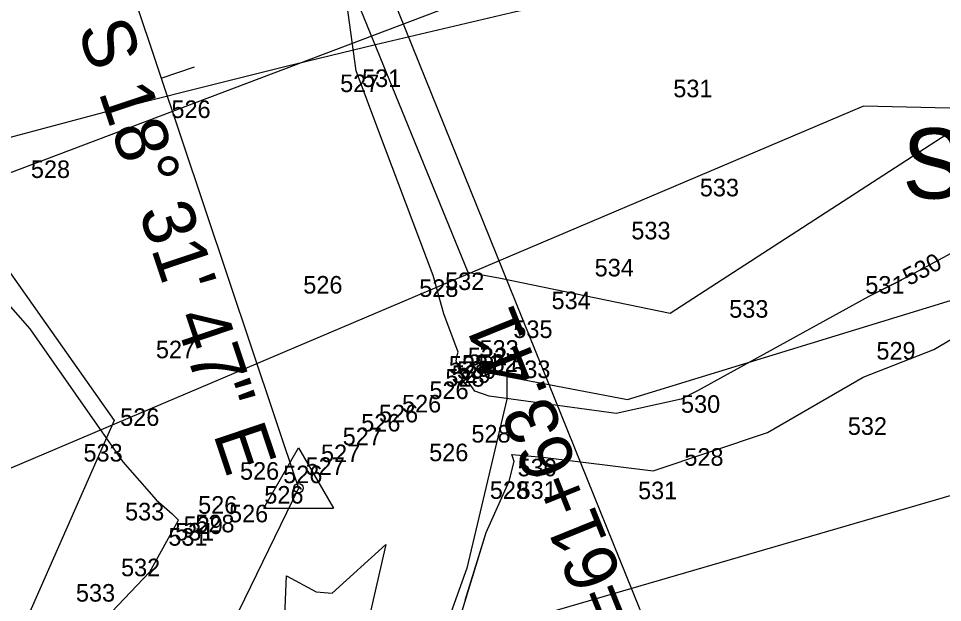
# Model space of a CAD drawing. Extents: x 1787461 to 1970323, y 938412 to 1118748.
# Drawn here: x 1967816.7 to 1967921.9, y 1117796.9 to 1117863.4 of the extents above; entities that cross this region are included whole.
import ezdxf

# ---------------------------------------------------------------- set-up
doc = ezdxf.new("R2010")
doc.units = 0
for name, color, linetype in [('Default', 7, 'Continuous'), ('HHA ADDITIONAL XSs', 7, 'Continuous'), ('Level 1', 7, 'Continuous'), ('RD_EX_DV_Prop', 7, 'Continuous'), ('RD_EX_H2O', 7, 'Continuous'), ('RD_EX_VEG', 7, 'Continuous'), ('RD_HC_CL', 7, 'Continuous'), ('RD_HC_CL_Rel', 7, 'Continuous'), ('RD_HC_Data', 7, 'Continuous'), ('RD_HC_Data_Tic', 7, 'Continuous'), ('RD_PD_Final_TrvlWay', 7, 'Continuous'), ('RD_SMD_Locator', 7, 'Continuous')]:
    doc.layers.add(name, color=color, linetype=linetype)

msp = doc.modelspace()

# ---------------------------------------------------------------- linework, layer by layer
at = {"layer": 'Default'}
for points in [[(1967867.59, 1117797.18), (1967869.95, 1117804.92), (1967872.58, 1117810.73), (1967873.16, 1117812.99), (1967872.89, 1117813.79), (1967876.43, 1117813.48), (1967888.97, 1117811.92), (1967902.02, 1117816.29), (1967912.9, 1117822.59), (1967920.97, 1117825.73), (1967929.46, 1117830.76), (1967935.78, 1117834.28), (1967952.17, 1117841.31), (1967957.87, 1117844.34), (1967974.87, 1117851.66), (1967974.98, 1117851.71), (1967977.62, 1117853.39), (1967984.02, 1117858.79), (1967988.88, 1117861.65), (1968005.7, 1117871.25), (1968008.59, 1117872.94), (1968022.11, 1117880.66), (1968026.51, 1117882.61), (1968036.54, 1117886.88)], [(1967867.59, 1117797.18), (1967869.95, 1117804.92), (1967872.58, 1117810.73), (1967873.16, 1117812.99), (1967872.89, 1117813.79), (1967876.43, 1117813.48), (1967888.97, 1117811.92), (1967902.02, 1117816.29), (1967912.9, 1117822.59), (1967920.97, 1117825.73), (1967929.46, 1117830.76), (1967935.78, 1117834.28), (1967952.17, 1117841.31), (1967957.87, 1117844.34), (1967974.87, 1117851.66), (1967974.98, 1117851.71), (1967977.62, 1117853.39), (1967984.02, 1117858.79), (1967988.88, 1117861.65), (1968005.7, 1117871.25), (1968008.59, 1117872.94), (1968022.11, 1117880.66), (1968026.51, 1117882.61), (1968036.54, 1117886.88)], [(1967867.59, 1117797.18), (1967869.95, 1117804.92), (1967872.58, 1117810.73), (1967873.16, 1117812.99), (1967872.89, 1117813.79), (1967876.43, 1117813.48), (1967888.97, 1117811.92), (1967902.02, 1117816.29), (1967912.9, 1117822.59), (1967920.97, 1117825.73), (1967929.46, 1117830.76), (1967935.78, 1117834.28), (1967952.17, 1117841.31), (1967957.87, 1117844.34), (1967974.87, 1117851.66), (1967974.98, 1117851.71), (1967977.62, 1117853.39), (1967984.02, 1117858.79), (1967988.88, 1117861.65), (1968005.7, 1117871.25), (1968008.59, 1117872.94), (1968022.11, 1117880.66), (1968026.51, 1117882.61), (1968036.54, 1117886.88)], [(1967867.59, 1117797.18), (1967869.95, 1117804.92), (1967872.58, 1117810.73), (1967873.16, 1117812.99), (1967872.89, 1117813.79), (1967876.43, 1117813.48), (1967888.97, 1117811.92), (1967902.02, 1117816.29), (1967912.9, 1117822.59), (1967920.97, 1117825.73), (1967929.46, 1117830.76), (1967935.78, 1117834.28), (1967952.17, 1117841.31), (1967957.87, 1117844.34), (1967974.87, 1117851.66), (1967974.98, 1117851.71), (1967977.62, 1117853.39), (1967984.02, 1117858.79), (1967988.88, 1117861.65), (1968005.7, 1117871.25), (1968008.59, 1117872.94), (1968022.11, 1117880.66), (1968026.51, 1117882.61), (1968036.54, 1117886.88)], [(1967867.59, 1117797.18), (1967869.95, 1117804.92), (1967872.58, 1117810.73), (1967873.16, 1117812.99), (1967872.89, 1117813.79), (1967876.43, 1117813.48), (1967888.97, 1117811.92), (1967902.02, 1117816.29), (1967912.9, 1117822.59), (1967920.97, 1117825.73), (1967929.46, 1117830.76), (1967935.78, 1117834.28), (1967952.17, 1117841.31), (1967957.87, 1117844.34), (1967974.87, 1117851.66), (1967974.98, 1117851.71), (1967977.62, 1117853.39), (1967984.02, 1117858.79), (1967988.88, 1117861.65), (1968005.7, 1117871.25), (1968008.59, 1117872.94), (1968022.11, 1117880.66), (1968026.51, 1117882.61), (1968036.54, 1117886.88)], [(1967867.59, 1117797.18), (1967869.95, 1117804.92), (1967872.58, 1117810.73), (1967873.16, 1117812.99), (1967872.89, 1117813.79), (1967876.43, 1117813.48), (1967888.97, 1117811.92), (1967902.02, 1117816.29), (1967912.9, 1117822.59), (1967920.97, 1117825.73), (1967929.46, 1117830.76), (1967935.78, 1117834.28), (1967952.17, 1117841.31), (1967957.87, 1117844.34), (1967974.87, 1117851.66), (1967974.98, 1117851.71), (1967977.62, 1117853.39), (1967984.02, 1117858.79), (1967988.88, 1117861.65), (1968005.7, 1117871.25), (1968008.59, 1117872.94), (1968022.11, 1117880.66), (1968026.51, 1117882.61), (1968036.54, 1117886.88)], [(1967925.22, 1117837.92), (1967918.26, 1117834.15), (1967913.54, 1117831.76), (1967894.04, 1117821.04), (1967892.19, 1117820.09), (1967884.77, 1117818.44), (1967870.31, 1117820.42), (1967868.68, 1117821), (1967866.81, 1117823.64), (1967866.54, 1117824.46), (1967866.67, 1117825.08), (1967866.78, 1117825.45), (1967865.14, 1117829.79), (1967863.91, 1117834.15), (1967857.75, 1117850.58), (1967855.17, 1117857.48), (1967853.01, 1117872.91)], [(1967917.26, 1117833.64), (1967913.54, 1117831.76), (1967894.04, 1117821.04), (1967892.19, 1117820.09), (1967884.77, 1117818.44), (1967870.31, 1117820.42), (1967868.68, 1117821), (1967866.81, 1117823.64), (1967866.54, 1117824.46), (1967866.67, 1117825.08), (1967866.78, 1117825.45), (1967865.14, 1117829.79), (1967863.91, 1117834.15), (1967857.75, 1117850.58), (1967855.17, 1117857.48), (1967853.01, 1117872.91)], [(1967917.26, 1117833.64), (1967913.54, 1117831.76), (1967894.04, 1117821.04), (1967892.19, 1117820.09), (1967884.77, 1117818.44), (1967870.31, 1117820.42), (1967868.68, 1117821), (1967866.81, 1117823.64), (1967866.54, 1117824.46), (1967866.67, 1117825.08), (1967866.78, 1117825.45), (1967865.14, 1117829.79), (1967863.91, 1117834.15), (1967857.75, 1117850.58), (1967855.17, 1117857.48), (1967853.01, 1117872.91)], [(1967917.26, 1117833.64), (1967913.54, 1117831.76), (1967894.04, 1117821.04), (1967892.19, 1117820.09), (1967884.77, 1117818.44), (1967870.31, 1117820.42), (1967868.68, 1117821), (1967866.81, 1117823.64), (1967866.54, 1117824.46), (1967866.67, 1117825.08), (1967866.78, 1117825.45), (1967865.14, 1117829.79), (1967863.91, 1117834.15), (1967857.75, 1117850.58), (1967855.17, 1117857.48), (1967853.01, 1117872.91)], [(1967917.26, 1117833.64), (1967913.54, 1117831.76), (1967894.04, 1117821.04), (1967892.19, 1117820.09), (1967884.77, 1117818.44), (1967870.31, 1117820.42), (1967868.68, 1117821), (1967866.81, 1117823.64), (1967866.54, 1117824.46), (1967866.67, 1117825.08), (1967866.78, 1117825.45), (1967865.14, 1117829.79), (1967863.91, 1117834.15), (1967857.75, 1117850.58), (1967855.17, 1117857.48), (1967853.01, 1117872.91)], [(1967917.26, 1117833.64), (1967913.54, 1117831.76), (1967894.04, 1117821.04), (1967892.19, 1117820.09), (1967884.77, 1117818.44), (1967870.31, 1117820.42), (1967868.68, 1117821), (1967866.81, 1117823.64), (1967866.54, 1117824.46), (1967866.67, 1117825.08), (1967866.78, 1117825.45), (1967865.14, 1117829.79), (1967863.91, 1117834.15), (1967857.75, 1117850.58), (1967855.17, 1117857.48), (1967853.01, 1117872.91)], [(1967917.26, 1117833.64), (1967913.54, 1117831.76), (1967894.04, 1117821.04), (1967892.19, 1117820.09), (1967884.77, 1117818.44), (1967870.31, 1117820.42), (1967868.68, 1117821), (1967866.81, 1117823.64), (1967866.54, 1117824.46), (1967866.67, 1117825.08), (1967866.78, 1117825.45), (1967865.14, 1117829.79), (1967863.91, 1117834.15), (1967857.75, 1117850.58), (1967855.17, 1117857.48), (1967853.01, 1117872.91)], [(1967865.81, 1117791.38), (1967869.95, 1117804.92), (1967872.58, 1117810.73), (1967873.16, 1117812.99), (1967872.89, 1117813.79), (1967876.43, 1117813.48), (1967888.97, 1117811.92), (1967902.02, 1117816.29), (1967912.9, 1117822.59), (1967920.97, 1117825.73), (1967929.46, 1117830.76), (1967935.78, 1117834.28), (1967952.17, 1117841.31), (1967957.87, 1117844.34), (1967974.87, 1117851.66), (1967974.98, 1117851.71), (1967977.62, 1117853.39), (1967984.02, 1117858.79), (1967988.88, 1117861.65), (1968005.7, 1117871.25)], [(1967801.88, 1117847.61), (1967810.59, 1117836.47), (1967817.97, 1117828.1), (1967825.91, 1117816.75), (1967828.59, 1117812.93), (1967832.36, 1117808.61), (1967834.19, 1117807.04), (1967834.93, 1117806.3), (1967834.88, 1117806.26), (1967831.61, 1117800.38), (1967827.33, 1117795.88), (1967821.98, 1117786.05), (1967816.55, 1117775), (1967811.53, 1117763.56), (1967808.3, 1117757.03), (1967806.64, 1117753.26), (1967802.17, 1117742.25), (1967796.95, 1117730.25), (1967792.24, 1117718.65), (1967787.4, 1117707.51)], [(1967801.88, 1117847.61), (1967810.59, 1117836.47), (1967817.97, 1117828.1), (1967825.91, 1117816.75), (1967828.59, 1117812.93), (1967832.36, 1117808.61), (1967834.19, 1117807.04), (1967834.93, 1117806.3), (1967834.88, 1117806.26), (1967831.61, 1117800.38), (1967827.33, 1117795.88), (1967821.98, 1117786.05), (1967816.55, 1117775), (1967811.53, 1117763.56), (1967808.3, 1117757.03), (1967806.64, 1117753.26), (1967802.17, 1117742.25), (1967796.95, 1117730.25), (1967792.24, 1117718.65), (1967787.4, 1117707.51)], [(1967801.88, 1117847.61), (1967810.59, 1117836.47), (1967817.97, 1117828.1), (1967825.91, 1117816.75), (1967828.59, 1117812.93), (1967832.36, 1117808.61), (1967834.19, 1117807.04), (1967834.93, 1117806.3), (1967834.88, 1117806.26), (1967831.61, 1117800.38), (1967827.33, 1117795.88), (1967821.98, 1117786.05), (1967816.55, 1117775), (1967811.53, 1117763.56), (1967808.3, 1117757.03), (1967806.64, 1117753.26), (1967802.17, 1117742.25), (1967796.95, 1117730.25), (1967792.24, 1117718.65), (1967787.4, 1117707.51)], [(1967801.88, 1117847.61), (1967810.59, 1117836.47), (1967817.97, 1117828.1), (1967825.91, 1117816.75), (1967828.59, 1117812.93), (1967832.36, 1117808.61), (1967834.19, 1117807.04), (1967834.93, 1117806.3), (1967834.88, 1117806.26), (1967831.61, 1117800.38), (1967827.33, 1117795.88), (1967821.98, 1117786.05), (1967816.55, 1117775), (1967811.53, 1117763.56), (1967808.3, 1117757.03), (1967806.64, 1117753.26), (1967802.17, 1117742.25), (1967796.95, 1117730.25), (1967792.24, 1117718.65), (1967787.4, 1117707.51)], [(1967801.88, 1117847.61), (1967810.59, 1117836.47), (1967817.97, 1117828.1), (1967825.91, 1117816.75), (1967828.59, 1117812.93), (1967832.36, 1117808.61), (1967834.19, 1117807.04), (1967834.93, 1117806.3), (1967834.88, 1117806.26), (1967831.61, 1117800.38), (1967827.33, 1117795.88), (1967821.98, 1117786.05), (1967816.55, 1117775), (1967811.53, 1117763.56), (1967808.3, 1117757.03), (1967806.64, 1117753.26), (1967802.17, 1117742.25), (1967796.95, 1117730.25), (1967792.24, 1117718.65), (1967787.4, 1117707.51)], [(1967801.88, 1117847.61), (1967810.59, 1117836.47), (1967817.97, 1117828.1), (1967825.91, 1117816.75), (1967828.59, 1117812.93), (1967832.36, 1117808.61), (1967834.19, 1117807.04), (1967834.93, 1117806.3), (1967834.88, 1117806.26), (1967831.61, 1117800.38), (1967827.33, 1117795.88), (1967821.98, 1117786.05), (1967816.55, 1117775), (1967811.53, 1117763.56), (1967808.3, 1117757.03), (1967806.64, 1117753.26), (1967802.17, 1117742.25), (1967796.95, 1117730.25), (1967792.24, 1117718.65), (1967787.4, 1117707.51)], [(1967810.59, 1117836.47), (1967817.97, 1117828.1), (1967825.91, 1117816.75), (1967828.59, 1117812.93), (1967832.36, 1117808.61), (1967834.19, 1117807.04), (1967834.93, 1117806.3), (1967834.88, 1117806.26), (1967831.61, 1117800.38), (1967827.33, 1117795.88), (1967821.98, 1117786.05), (1967816.55, 1117775)], [(1967825.01, 1117755.18), (1967834.57, 1117771.02), (1967835.27, 1117771.98), (1967838.28, 1117781.65), (1967846.84, 1117790.9), (1967847.21, 1117799.97), (1967850.61, 1117798.14), (1967852.43, 1117798), (1967858.52, 1117803.53), (1967855.88, 1117791.92), (1967854.34, 1117786.82), (1967849.71, 1117768.33), (1967849.28, 1117766.59), (1967847.71, 1117761.38), (1967838.96, 1117746.55), (1967835.72, 1117740.01), (1967826.65, 1117725.53), (1967826.39, 1117724.96), (1967825.77, 1117723.3), (1967824.68, 1117721.97), (1967823.26, 1117725.85), (1967825.32, 1117727.69), (1967825.09, 1117747.68), (1967825.01, 1117755.18)], [(1967825.01, 1117755.18), (1967834.57, 1117771.02), (1967835.27, 1117771.98), (1967838.28, 1117781.65), (1967846.84, 1117790.9), (1967847.21, 1117799.97), (1967850.61, 1117798.14), (1967852.43, 1117798), (1967858.52, 1117803.53), (1967855.88, 1117791.92), (1967854.34, 1117786.82), (1967851.45, 1117775.29)], [(1967825.01, 1117755.18), (1967834.57, 1117771.02), (1967835.27, 1117771.98), (1967838.28, 1117781.65), (1967846.84, 1117790.9), (1967847.21, 1117799.97), (1967850.61, 1117798.14), (1967852.43, 1117798), (1967858.52, 1117803.53), (1967855.88, 1117791.92), (1967854.34, 1117786.82), (1967851.45, 1117775.29)], [(1967825.01, 1117755.18), (1967834.57, 1117771.02), (1967835.27, 1117771.98), (1967838.28, 1117781.65), (1967846.84, 1117790.9), (1967847.21, 1117799.97), (1967850.61, 1117798.14), (1967852.43, 1117798), (1967858.52, 1117803.53), (1967855.88, 1117791.92), (1967854.34, 1117786.82), (1967851.45, 1117775.29)], [(1967825.01, 1117755.18), (1967834.57, 1117771.02), (1967835.27, 1117771.98), (1967838.28, 1117781.65), (1967846.84, 1117790.9), (1967847.21, 1117799.97), (1967850.61, 1117798.14), (1967852.43, 1117798), (1967858.52, 1117803.53), (1967855.88, 1117791.92), (1967854.34, 1117786.82), (1967851.45, 1117775.29)], [(1967825.01, 1117755.18), (1967834.57, 1117771.02), (1967835.27, 1117771.98), (1967838.28, 1117781.65), (1967846.84, 1117790.9), (1967847.21, 1117799.97), (1967850.61, 1117798.14), (1967852.43, 1117798), (1967858.52, 1117803.53), (1967855.88, 1117791.92), (1967854.34, 1117786.82), (1967851.45, 1117775.29)], [(1967825.01, 1117755.18), (1967834.57, 1117771.02), (1967835.27, 1117771.98), (1967838.28, 1117781.65), (1967846.84, 1117790.9), (1967847.21, 1117799.97), (1967850.61, 1117798.14), (1967852.43, 1117798), (1967858.52, 1117803.53), (1967855.88, 1117791.92), (1967854.34, 1117786.82), (1967851.45, 1117775.29)]]:
    msp.add_lwpolyline(points, dxfattribs=at)
at = {"layer": 'HHA ADDITIONAL XSs'}
msp.add_lwpolyline([(1969308.89, 1117819.66), (1967912.94, 1117853.44), (1967442.55, 1117653.93), (1967107.32, 1117508.48)], dxfattribs=at)
for radius in [1667.02, 1607.02]:
    msp.add_arc((1968231.34, 1116297.54), radius, 87.72663, 111.99584, dxfattribs=at)
at = {"layer": 'Level 1'}
msp.add_lwpolyline([(1968654.57, 1117840.68), (1968058.24, 1117848.48), (1967686.38, 1117740.3), (1966964.76, 1117453.35)], dxfattribs=at)
at = {"layer": 'RD_EX_DV_Prop'}
for p, q in [((1967823.97, 1117883.41), (1967848.59, 1117809.96)), ((1967848.59, 1117809.96), (1967728.08, 1117563.01))]:
    msp.add_line(p, q, dxfattribs=at)
at = {"layer": 'RD_EX_H2O'}
for points in [[(1967867.87, 1117834.54), (1967871.59, 1117833.85), (1967890.93, 1117829.89), (1967921.85, 1117849.89), (1967964.79, 1117874.79), (1967977.94, 1117879.79), (1968015.09, 1117899.77), (1968057.26, 1117913.2)], [(1967837.05, 1117908.32), (1967851.7, 1117885.92), (1967854.61, 1117866.99), (1967867.87, 1117834.54)], [(1967872.32, 1117822.66), (1967886.05, 1117820.05), (1967930.51, 1117833.68), (1967976.62, 1117854.05), (1967987.44, 1117860.04), (1968022.07, 1117880.44), (1968056.79, 1117893.09)], [(1967793.07, 1117884.81), (1967795.4, 1117862.79), (1967808.44, 1117844.76), (1967827.6, 1117817.64), (1967803.85, 1117763.92), (1967785.1, 1117717.4), (1967778.96, 1117698.7), (1967761.45, 1117660.55), (1967735.16, 1117625.66), (1967726.1, 1117620.57), (1967713.81, 1117582.71), (1967729.78, 1117524.09), (1967774.63, 1117477.47), (1967792.06, 1117468.24), (1967815.16, 1117463.54)], [(1967872.32, 1117822.66), (1967872.31, 1117820.09), (1967867.75, 1117800.84), (1967855.06, 1117765.41), (1967833.55, 1117731.08), (1967814.13, 1117687.88), (1967798.73, 1117637.75), (1967777.02, 1117596.99), (1967770.1, 1117591.47), (1967755.23, 1117573.96), (1967763.13, 1117553.21), (1967794.74, 1117526.69), (1967804.69, 1117522.56), (1967827.72, 1117512.92)]]:
    msp.add_lwpolyline(points, dxfattribs=at)
at = {"layer": 'RD_EX_VEG'}
msp.add_lwpolyline([(1967302.31, 1117610.37), (1967337.76, 1117649.58), (1967352.05, 1117663.92), (1967393.53, 1117676.59), (1967483.38, 1117717.02), (1967710.35, 1117806.03), (1967888.86, 1117873.57), (1967928.06, 1117882.04), (1967957.92, 1117887.35), (1967975.7, 1117893.86), (1968013.09, 1117903.71), (1968102.91, 1117899.22), (1968154.08, 1117904.84), (1968208.62, 1117905.24), (1968319.32, 1117902.87), (1968421.81, 1117901.58), (1968527.92, 1117886.31)], dxfattribs=at)
at = {"layer": 'RD_HC_CL'}
for p, q in [((1967803.58, 1117944.23), (1967848.59, 1117809.96)), ((1967848.59, 1117809.96), (1967728.08, 1117563.01))]:
    msp.add_line(p, q, dxfattribs=at)
at = {"layer": 'RD_HC_CL_Rel'}
msp.add_arc((1968231.34, 1116297.54), 1637.02, 87.72663, 111.99584, dxfattribs=at)
at = {"layer": 'RD_HC_Data'}
for p, q in [((1967848.24, 1117893.22), (1967891.71, 1117785.61)), ((1967844.62, 1117807.67), (1967848.59, 1117814.55)), ((1967848.59, 1117814.55), (1967852.56, 1117807.67)), ((1967844.62, 1117807.67), (1967852.56, 1117807.67))]:
    msp.add_line(p, q, dxfattribs=at)
msp.add_circle((1967848.59, 1117809.96), 0.529, dxfattribs=at)
at = {"layer": 'RD_HC_Data_Tic'}
msp.add_line((1967832.94, 1117856.65), (1967836.73, 1117857.92), dxfattribs=at)
at = {"layer": 'RD_PD_Final_TrvlWay'}
for radius in [1648.02, 1626.02]:
    msp.add_arc((1968231.34, 1116297.54), radius, 87.72663, 111.99584, dxfattribs=at)
at = {"layer": 'RD_SMD_Locator'}
msp.add_circle((1967848.59, 1117809.96), 0.001, dxfattribs=at)

# ---------------------------------------------------------------- texts
at = {"layer": 'Default'}
for s, p in [('527', (1967853.33, 1117855.05)), ('531', (1967855.83, 1117855.63)), ('531', (1967891.28, 1117854.46)), ('526', (1967834.11, 1117852.1)), ('528', (1967818.1, 1117845.27)), ('533', (1967894.3, 1117843.18)), ('533', (1967886.5, 1117838.28)), ('534', (1967882.32, 1117834.06)), ('526', (1967849.13, 1117832.11)), ('528', (1967862.34, 1117831.73)), ('532', (1967865.29, 1117832.51)), ('531', (1967913.15, 1117832.1)), ('534', (1967877.41, 1117830.33)), ('533', (1967897.65, 1117829.36)), ('535', (1967873.06, 1117827.05)), ('527', (1967832.34, 1117824.74)), ('533', (1967869.21, 1117824.8)), ('529', (1967914.42, 1117824.59)), ('532', (1967867.88, 1117823.93)), ('532', (1967869.1, 1117823.19)), ('528', (1967865.72, 1117822.99)), ('530', (1967866.64, 1117822.4)), ('531', (1967867.2, 1117823.13)), ('533', (1967872.82, 1117822.49)), ('528', (1967865.32, 1117821.51)), ('529', (1967866.04, 1117821.93)), ('526', (1967863.5, 1117820.1)), ('526', (1967860.38, 1117818.57)), ('530', (1967892.16, 1117818.53)), ('526', (1967828.27, 1117817.04)), ('526', (1967857.75, 1117817.44)), ('526', (1967855.73, 1117816.4)), ('532', (1967911.16, 1117816.02)), ('527', (1967853.62, 1117814.84)), ('528', (1967868.28, 1117815.14)), ('533', (1967824.09, 1117812.98)), ('527', (1967851.15, 1117812.92)), ('526', (1967863.47, 1117813.02)), ('528', (1967892.54, 1117812.5)), ('526', (1967841.92, 1117810.91)), ('526', (1967846.84, 1117810.52)), ('527', (1967849.4, 1117811.46)), ('530', (1967873.55, 1117811.3)), ('528', (1967870.38, 1117808.73)), ('531', (1967873.54, 1117808.73)), ('531', (1967887.27, 1117808.69)), ('526', (1967844.69, 1117808.19)), ('526', (1967837.15, 1117807.04)), ('533', (1967828.83, 1117806.28)), ('526', (1967840.67, 1117806.06)), ('529', (1967835.5, 1117804.73)), ('528', (1967836.83, 1117804.92)), ('531', (1967833.76, 1117803.4)), ('531', (1967834.53, 1117803.99)), ('532', (1967828.37, 1117799.92)), ('533', (1967823.23, 1117797.03))]:
    msp.add_text(s, height=2, dxfattribs=at).set_placement(p)
msp.add_text('530', height=2, rotation=28.1863, dxfattribs=at).set_placement((1967918.12, 1117832.95))
msp.add_text('530', height=2, rotation=28.1863, dxfattribs=at).set_placement((1967918.12, 1117832.95))
msp.add_text('530', height=2, rotation=28.1863, dxfattribs=at).set_placement((1967918.12, 1117832.95))
msp.add_text('530', height=2, rotation=28.1863, dxfattribs=at).set_placement((1967918.12, 1117832.95))
msp.add_text('530', height=2, rotation=28.1863, dxfattribs=at).set_placement((1967918.12, 1117832.95))
msp.add_text('530', height=2, rotation=28.1863, dxfattribs=at).set_placement((1967918.12, 1117832.95))
at = {"layer": 'HHA ADDITIONAL XSs'}
msp.add_text('Supplemental XSC 02 Creek Station Approximately 26+35', height=8, dxfattribs=at).set_placement((1967917.36, 1117842.93))
at = {"layer": 'RD_HC_Data'}
for s, rotation, p in [('S 18%%d 31\' 47" E', 288.5298, (1967823.37, 1117862.25)), ('PC=61+63.41', 111.9958, (1967891.47, 1117785.18))]:
    msp.add_text(s, height=6, rotation=rotation, dxfattribs=at).set_placement(p)

doc.saveas('drawing.dxf')
